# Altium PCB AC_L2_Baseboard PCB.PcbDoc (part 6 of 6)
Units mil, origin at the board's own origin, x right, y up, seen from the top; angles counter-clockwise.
Board outline 7290 x 7055 mil, 4 copper layers (Top Layer, Layer 1, Layer 2, Bottom Layer), stack 70.356 mil thick; 510 components, 285 nets, 1364 pads, 522 vias.
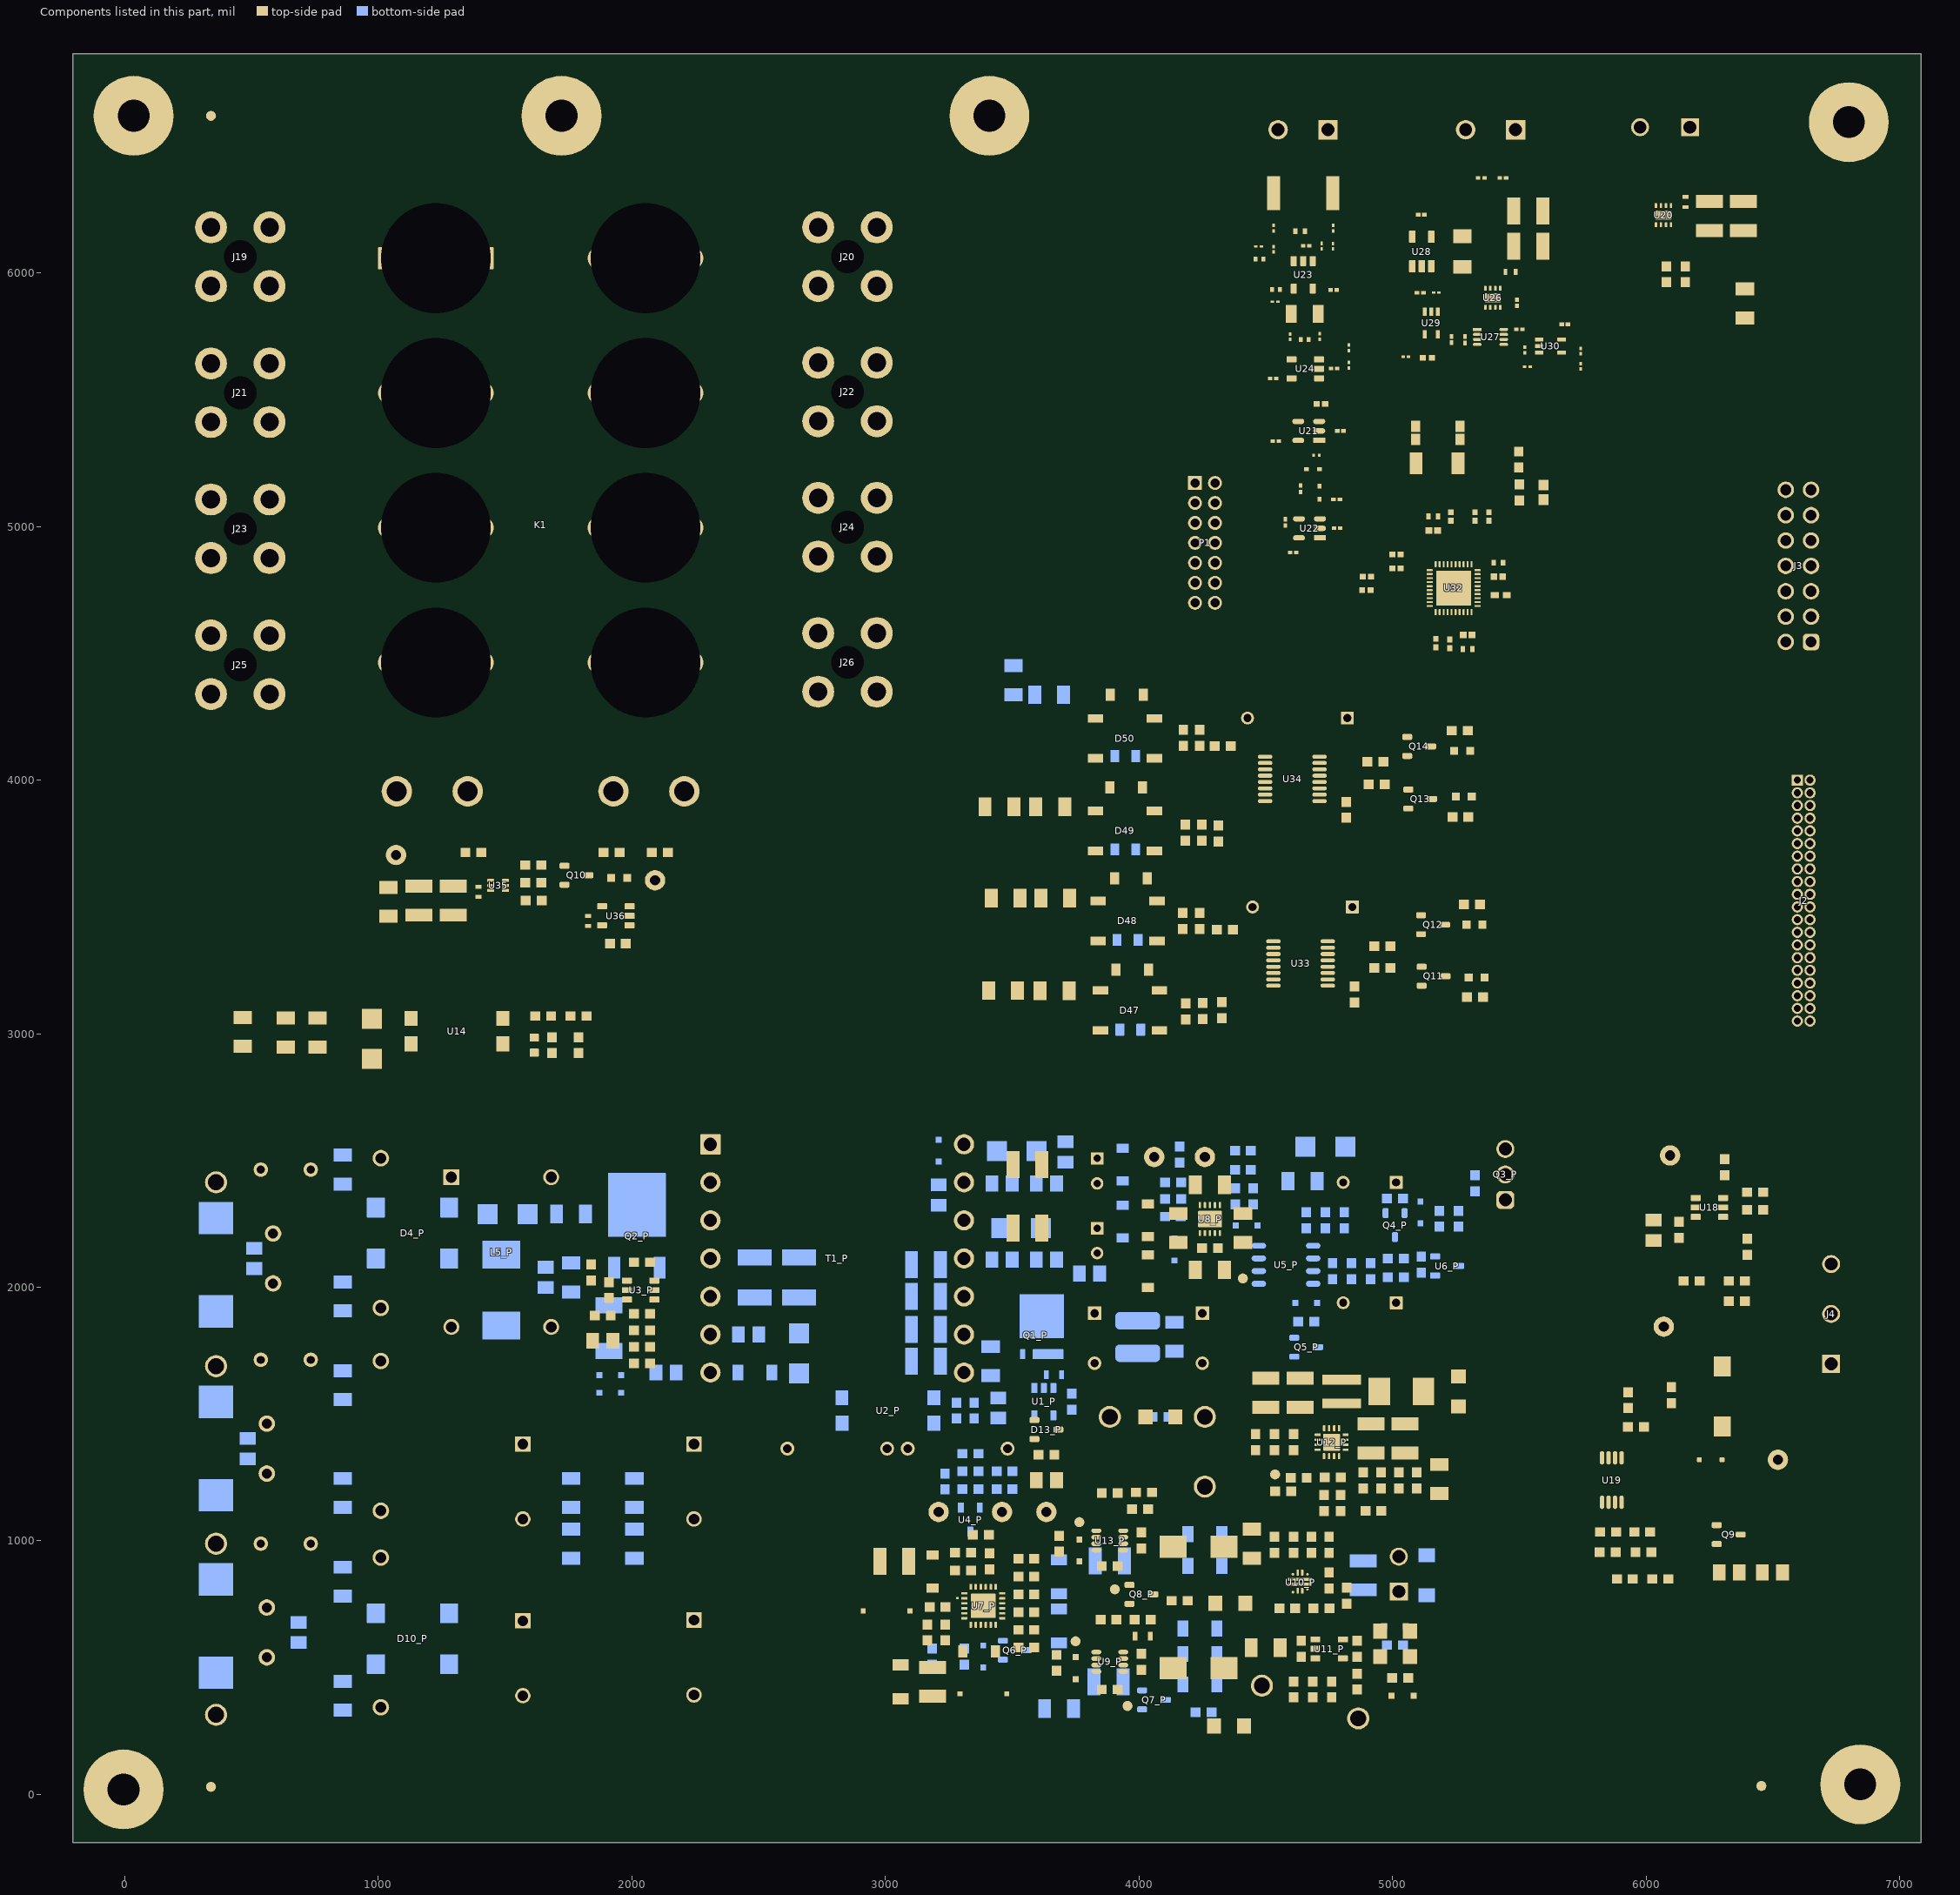
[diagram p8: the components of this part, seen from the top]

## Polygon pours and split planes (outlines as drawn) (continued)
NetC21_P_1 on Layer 2 "LAYER_2_NETC21_P_1_P1274" (solid, pour order 1274): 3195,2144 3270,2144 3290,2164 3355,2164 3700,1819 4070,1819 4080,1809 4080,1714 4005,1639 3205,1639 3190,1654 3190,2139
AGND1 on Layer 2 "LAYER_2_AGND1_P1262" (solid, pour order 1262): 3340,984 3560,984 3610,934 3610,714 3500,604 3372,604 3242,734 3166,734 3166,810
NetC38_P_1 on Layer 2 "LAYER_2_NETC38_P_1_P1272" (solid, pour order 1272): 4910,2464 4935,2489 5075.94,2489 5105.95,2459 5105.95,2134.95 4860,1889 4750.5,1889 4731,1908.5 4731,2110 4910,2289
Vbackup on Layer 2 "LAYER_2_VBACKUP_P1266" (solid, pour order 1266): 4635,2442 4682,2489 4860,2489 4885,2464 4885,2289 4710,2114 4710,1858.68 4735.79,1832.9 4866.1,1832.9 4885,1814 4885,1663.31 4480,1663.31 4480,2209 4635,2364
N_OUT on Layer 2 "LAYER_2_N_OUT_P1426" (solid, pour order 1426): 1825,4667.26 3030,4667.26 3070,4627.26 3070,4327.26 3015,4272.26 1825,4272.26 1785,4312.26 1785,4627.26
LINE3_OUT on Layer 2 "LAYER_2_LINE3_OUT_P1424" (solid, pour order 1424): 1832.5,5195 3037.5,5195 3077.5,5155 3077.5,4855 3022.5,4800 1832.5,4800 1792.5,4840 1792.5,5155
LINE2_OUT on Layer 2 "LAYER_2_LINE2_OUT_P1422" (solid, pour order 1422): 1820,5725 3025,5725 3065,5685 3065,5385 3010,5330 1820,5330 1780,5370 1780,5685
LINE1_OUT on Layer 2 "LAYER_2_LINE1_OUT_P1420" (solid, pour order 1420): 1809.7,6260 3014.7,6260 3054.7,6220 3054.7,5920 2999.7,5865 1809.7,5865 1769.7,5905 1769.7,6220
N_IN on Layer 2 "LAYER_2_N_IN_P1418" (solid, pour order 1418): 275,4655 1480,4655 1520,4615 1520,4315 1465,4260 275,4260 235,4300 235,4615
LINE3_IN on Layer 2 "LAYER_2_LINE3_IN_P1416" (solid, pour order 1416): 270,5185 1475,5185 1515,5145 1515,4845 1460,4790 270,4790 230,4830 230,5145
LINE2_IN on Layer 2 "LAYER_2_LINE2_IN_P1414" (solid, pour order 1414): 285,5730 1490,5730 1530,5690 1530,5390 1475,5335 285,5335 245,5375 245,5690
LINE1_IN on Layer 2 "LAYER_2_LINE1_IN_P1412" (solid, pour order 1412): 285,6265 1490,6265 1530,6225 1530,5925 1475,5870 285,5870 245,5910 245,6225
NetD4_P_4 on Layer 2 "LAYER_2_NETD4_P_4_P1282" (solid, pour order 1282): 940,2369 1045,2369 1045,2259 940,2259
NetC13_P_2 on Layer 2 "LAYER_2_NETC13_P_2_P1280" (solid, pour order 1280): 1485,1214 1485,589 2385,589 2385,1214
no net on Layer 2 "LAYER_2_NONET_P1278" (solid, pour order 1278): 1810,2589 2460,2589 2485,2564 2485,2364 2460,2339 2260,2339 2210,2289 2210,2214 2185,2189 1810,2189 1785,2214 1785,2564
NetC6_P_1 on Layer 2 "LAYER_2_NETC6_P_1_P1276" (solid, pour order 1276): 1825,1499 1585,1739 1585,2214 1735,2364 1735,2514 1710,2539 1485,2539 1360,2414 1360,2014 1410,1964 1410,1764 1335,1689 1335,1364 1410,1289 2335,1289 2530,1484 2530,1984 2475,2039 2235,2039 2235,1499
12V_In on Layer 2 "LAYER_2_12V_IN_P1270" (solid, pour order 1270): 3790,1979 4105,1979 4130,1954 4300,1954 4335,1919 4335,1454 4320,1439 4135,1439 4090,1484 4090,1829 3825,1829 3782.5,1829 3765,1840.67 3765,1954
NetC50_P_1 on Layer 2 "LAYER_2_NETC50_P_1_P1268" (solid, pour order 1268): 3560,464 3600,424 3600,274 3590,264 2935,264 2860,339 2860,589 2885,614 2985,614 3010,589 3135,464
AGND2 on Layer 2 "LAYER_2_AGND2_P1264" (solid, pour order 1264): 4675,1454 4870,1454 5010,1314 5010,1184 4960,1134 4635,1134 4610,1159 4610,1389
+12V on Layer 2 "LAYER_2_+12V_P1260" (solid, pour order 1260): 5135.5,1216.72 5138.23,1214 5260,1214 5285,1189 5285,1039 5260,1014 4960,1014 4785,839 4665,839 4606.22,780.22 4418.78,780.22 4410,789 4410,1039 4360,1089 4285,1089 3860,664 3660,664 3660,995.5 3853.5,1189 4185,1189 4210,1164 4310,1164 4360,1214 4535,1214 4560,1189 4560,1139 4585,1114 5024.62,1114 5127.35,1216.72
5V on Layer 2 "LAYER_2_5V_P1258" (solid, pour order 1258): 4259,1064 4385,1064 4385,739 4260,614 4110,464 4110,339 4035,264 3785,264 3760,289 3760,589 3810,639 3834,639

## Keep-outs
Keep-Out Layer:
  text ".Layer_Name" at 577,-858.49 h60

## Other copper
Top Layer:
  text ".Layer_Name" at 577,-858.49 h60
Layer 1:
  text ".Layer_Name" at 580,-850 h60
Layer 2:
  text ".Layer_Name" at 580,-850 h60
Bottom Layer:
  text ".Layer_Name" at 577,-858.49 h60

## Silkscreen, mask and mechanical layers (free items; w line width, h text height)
Top Overlay:
  lines w10: 1795,1500 1795,1665 1840,1710 1935,1710 1990,1655 1990,1615 1990,1490 1965,1465 1940,1440 1845,1440 ; 1990,1600 2040,1600 2055,1615 2055,1665 ; 2045,1655 2055,1665 ; 2065,1655 2055,1665 ; 2975,1165 3080,1165 ; 3060,1145 3080,1165 ; 3060,1185 3080,1165 ; 3075,550 3100,575 ; 3075,600 3100,575 ; 3520,495 3540,515 ; 3560,495 3540,515 ; 3905,230 3900,235 3900,265 4015,265 4065,315 4220,315 4230,305 ; 3930,285 3950,305 ; 3950,265 3950,305 ; 3955,195 3960,190 3995,190 4030,155 4030,60 4115,-25 4290,-25 4315,0 4315,195 4295,215 ; 3970,285 3950,305 ; 4430,2490 4445,2475 ; 4445,2640 4445,2475 ; 4460,2490 4445,2475 ; 4790,3160 4445,3160 4410,3130 4405,2675 4425,2650 4705,2650 4895,2840 4895,2985 4895,3025 ; 5175,575 5150,600 ; 5175,625 5150,600 ; 5200,600 5150,600 ; 5205,1350 5180,1375 ; 5205,1400 5180,1375 ; 5255,1375 5180,1375 ; 5260,1225 5260,1080 5300,1040 5615,1040 5740,1165 5740,1195 5740,1430 5660,1510 5420,1510 5375,1510 5260,1395 5260,1310 ; 5355,1565 5335,1585 ; 5355,1605 5335,1585 ; 5470,1690 5470,1585 5335,1585 ; 2900,450 3025,575 3100,575 ; 2900,450 2900,325 2925,300 2925,250 2800,125 2600,125 2575,150 2575,475 2600,500 2850,500 2900,450 ; 3540,515 3540,420 3580,380 ; 3580,380 3570,370 3570,40 3595,15 3910,15 3935,40 3935,190 3915,210 3835,210 3765,280 3765,355 3725,395 3595,395 3580,380 ; 2710,1050 2710,1180 2710,1185 2735,1210 2955,1210 2975,1190 2975,1050 2960,1035 2725,1035 2715,1045 2710,1050 ; 5235,265 5235,915 5235,950 5285,1000 5300,1000 5600,1000 5675,925 5675,800 5850,625 5925,625 5975,575 5975,250 5925,200 5300,200 5235,265 ; 5385,1690 5385,1795 5385,1905 5400,1905 5805,1905 5805,1690 5400,1690 5385,1690
  text "O1" at 6148,6762 h20
  text "O2" at 5957,6757 h20
  text "AC+" at 4708,6737 h20
  text "AC-" at 4535,6736 h20
  text "DC-" at 5261,6736 h20
  text "DC+" at 5450,6736 h20
  text "Plug" at 5683,6640 h50
  text "RCD DC" at 4880,6552 h50
  text "RCD AC" at 4148,6539 h50
  text "Lock" at 5681,6538 h50
  text "AC Input" at 275,6355 h60
  text "AC Output" at 2659,6355 h60
  text "L1" at 85,6066 h60
  text "L1" at 3117,6059 h60
  text "L2" at 77,5532 h60
  text "L2" at 3109,5525 h60
  text "E-meter" at 6486,5327 h50
  text "L3" at 69,4985 h60
  text "L3" at 3101,4978 h60
  text "N" at 77,4446 h60
  text "N" at 3109,4439 h60
  text "Weld Detection" at 4950,3655 h60
  text "Relay Drive" at 2175,3435 h60
  text "ZC HPGP" at 1899,2950.7 h60
  text "-12Va" at 3985,2640 h40
  text "+12Va" at 4205,2640 h40
  text "CP" at 6906,2069 h50
  text "PE" at 6907,1866 h50
  text "PP" at 6918,1673 h50
  text "GND" at 3800,1435 h40 r90
  text "+12Vp" at 4390,1405 h40 r90
  text "+5V" at 4210,1300 h40
  text "GND" at 5220,950 h40 r90
  text "12Vext" at 5215,705 h40 r90
  text "3.3V" at 4470,290 h40
  text "1.8V" at 4810,160 h40
  text ".Layer_Name" at 577,-858.49 h60
Bottom Overlay:
  lines w10: 2850,1250 3150,1250 ; 3125,1225 3150,1250 ; 3125,1275 3150,1250 ; 3210,1415 3210,1365 3155,1310 3155,1085 3235,1005 3510,1005 3560,1055 3560,1445 3505,1500 3505,1820 3485,1840 3360,1840 ; 3235,1595 3265,1625 ; 3302.5,1722.5 3345,1765 ; 4265,2315 4265,2445 ; 4280,2580 4315,2615 4325,2625 5300,2625 5325,2600 5365,2560 5365,2535 5365,2040 5275,1950 5050,1950 ; 4300,2260 4425,2135 4425,1850 4550,1725 4572.4,1725 ; 4715,1725 4800,1725 4975,1900 ; 5940,2046 5915,2071 ; 5940,2096 5915,2071 ; 6090,2071 5915,2071 ; 2480,580 2480,845 2515,880 2515,1085 2570,1140 2570,1175 2570,1200 2650,1280 2650,1320 2650,1340 2665,1355 2790,1355 2810,1335 2840,1305 2840,985 2865,960 2865,570 2840,545 2515,545 2480,580 ; 5915,2346 6090,2171 6090,1905 6274,1721 6390,1721 6665,1996 6915,1996 6965,2046 6965,2621 6965,2646 6940,2671 5965,2671 5915,2621 5915,2346
  text ".Layer_Name" at 577,-858.49 h60
Top Paste:
  text ".Layer_Name" at 577,-858.49 h60
Bottom Paste:
  text ".Layer_Name" at 577,-858.49 h60
Top Solder:
  text ".Layer_Name" at 577,-858.49 h60
  text ".Layer_Name" at 577,-858.49 h60
Bottom Solder:
  text ".Layer_Name" at 577,-858.49 h60
Drill Guide:
  text ".Layer_Name" at 577,-858.49 h60
M1 Board Outline:
  the board outline again, w10
  text ".Layer_Name" at 577,-858.49 h60
M2 Board Dimensions:
  rectangle: 0,-275 125,-150
  rectangle: 125,-400 500,-275
  lines w7: 0,-275 1000,-275 ; 125,-400 125,-150 ; 250,-400 250,-150 ; 500,-400 500,-150 ; 750,-400 750,-150 ; 0,-400 1000,-400 1000,-150 0,-150 0,-400
  text ".Layer_Name" at 577,-858.49 h60
M3 3D STEP Top:
  text ".Layer_Name" at 577,-858.49 h60
M4 3D STEP Bottom:
  text ".Layer_Name" at 577,-858.49 h60
M5 Assembly Top:
  circle w10: c2210,2564 r35.36
  lines w10: -292,-930.17 6308,-930.17 ; -292,-726.83 6310,-726.83 ; -292,-523.5 -292,-1133.5 3713,-1133.5 6310,-1133.5 6310,-523.5 -291.5,-523.5 -291.5,-1133.5 1284,-1133.5 ; 2173,-1133.5 2173,-523.5 ; 3440,-726.83 3440,-523.5 ; 4280,-726.83 4280,-523.5 ; 4902,-1140 4902,-937.17
  text "L1" at 185,2405 h60
  text "L2" at 165,1655 h60
  text "L3" at 160,970 h60
  text "N" at 215,285 h60
  text "COMPONENTS MARKED 'DNP' SHOULD NOT BE POPULATED." at 1153.5,-318.5 h60
  text "ASSEMBLY VARIANT:" at 1153,-434 h60
  text ".VariantName" at 2189,-434 h60
  text "PCB VIEWED FROM TOP SIDE" at -228.5,-655.67 h60
  text "BOARD #:" at 2248,-655.67 h60
  text ".PRJ_Number" at 2793.5,-655.67 h60
  text "REV:" at 3638,-655.67 h60
  text ".PCB_Rev" at 3929.5,-655.67 h60
  text "SVN REV:" at 4476,-655.67 h60
  text ".VersionControl_RevNumber" at 4982,-655.67 h60
  text "TID #:" at 2248,-859 h60
  text ".TID" at 2793.5,-859 h60
  text "PLOT NAME =" at -228.5,-1064.34 h60
  text ".plot_File_Name" at 577,-1064.34 h60
  text "GENERATED    :" at 2250,-1064.34 h60
  text ".Print_Date" at 3119.5,-1064.34 h60
  text ".Print_Time" at 3848.5,-1064.34 h60
  text "TEXAS INSTRUMENTS" at 5113,-1064.34 h60
M6 Assembly Bottom:
  lines w10: -292.5,-727.33 6309.5,-727.33 ; -290.5,-930.67 6309.5,-930.67 ; 1115.5,-1140.5 1115.5,-937.67 ; 1737.5,-727.33 1737.5,-524 ; 2577.5,-727.33 2577.5,-524 ; 3844.5,-1134 3844.5,-524 ; 4733.5,-1134 6309,-1134 6309,-524 -292.5,-524 -292.5,-1134 2304.5,-1134 6309.5,-1134 6309.5,-524
  text "COMPONENTS MARKED 'DNP' SHOULD NOT BE POPULATED." at 6102,-318 h60
  text ".VariantName" at 5058,-434 h60
  text "ASSEMBLY VARIANT:" at 6097,-434 h60
  text ".VersionControl_RevNumber" at 1035.5,-656.17 h60
  text "SVN REV:" at 1541.5,-656.17 h60
  text ".PCB_Rev" at 2088,-656.17 h60
  text "REV:" at 2379.5,-656.17 h60
  text ".PRJ_Number" at 3224,-656.17 h60
  text "BOARD #:" at 3769.5,-656.17 h60
  text "PCB VIEWED FROM BOTTOM SIDE" at 6246,-656.17 h60
  text ".TID" at 3224,-859.5 h60
  text "TID #:" at 3769.5,-859.5 h60
  text "TEXAS INSTRUMENTS" at 904.5,-1064.84 h60
  text ".Print_Time" at 2169,-1064.84 h60
  text ".Print_Date" at 2898,-1064.84 h60
  text "GENERATED    :" at 3767.5,-1064.84 h60
  text ".plot_File_Name" at 5440.5,-1064.84 h60
  text "PLOT NAME =" at 6246,-1064.84 h60
M9 Title Sheet:
  drawing of 57 lines, arcs and shapes, not listed
  text "1" at 539.84,8236.5 h70
  text "2" at 3035.5,8236.5 h70
  text "3" at 5524.84,8236.5 h70
  text "4" at 8031.51,8236.5 h70
  text "5" at 10530.5,8236.5 h70
  text "6" at 13035.5,8236.5 h70
  text "A" at -416.5,5193.5 h70
  text "A" at 14383.5,5193.5 h70
  text "B" at -416.5,4513.5 h70
  text "B" at 14383.5,4513.5 h70
  text "C" at -416.5,2138.5 h70
  text "C" at 14383.5,2138.5 h70
  text "PROJECT TITLE:" at 11343.5,277.5 h45
  text ".PRJ_Title" at 11393.5,144.17 h70
  text "DESIGNED FOR:" at 11343.5,-23.5 h45
  text ".PRJ_Customer" at 11393.5,-163.5 h70
  text "D" at -416.5,-231.5 h70
  text "D" at 14383.5,-231.5 h70
  text "FILE NAME:" at 11343.5,-323.5 h45
  text ".PCB_File_Name_No_Path" at 11393.5,-443.5 h70
  text "Texas Instruments (TI) and/or its licensors do not warrant the accuracy or completeness of this specification" at 6374,-605.34 h45
  text "ENGINEER:" at 11343.5,-613.5 h45
  text "LAYOUT BY:" at 12848.5,-613.5 h45
  text "or any information contained therein. TI and/or its licensors do not warrant that this design will meet" at 6329.01,-718 h45
  text ".PRJ_Engineer" at 11393.5,-768.49 h70
  text ".PCB_Layout" at 12899,-768.49 h70
  text "the specifications, will be suitable for your application or fit for any particular purpose, or will operate in" at 6329.01,-830.67 h45
  text ".Layer_Name" at 577,-858.49 h60
  text "ALTIUM DESIGNER VERSION:" at 12848.5,-923.5 h45
  text "an implementation. TI and/or its licensors do not warrant that the design is production worthy. You should" at 6329.01,-943.33 h45
  text "completely validate and test your design implementation to confirm the system functionality for your application." at 6374,-1056 h45
  text ".print_Scale" at 11393.5,-1056.83 h70
  text ".Application_BuildNumber" at 12899,-1056.83 h70
  text "1" at 739.84,-1263.5 h70
  text "2" at 3235.5,-1263.5 h70
  text "3" at 5724.84,-1263.5 h70
  text "4" at 8231.51,-1263.5 h70
  text "5" at 10730.5,-1263.5 h70
  text "6" at 13235.5,-1263.5 h70
M10 Fab Notes:
  drawing of 189 lines, arcs and shapes, not listed
  text "DESIGN INFORMATION" at 12368.02,6361.17 h60
  text "MIN. TRACK WIDTH:" at 11723.46,6229.05 h60
  text "8" at 12819.7,6229.05 h60
  text "MIL" at 12974.46,6229.05 h60
  text "MIN. CLEARANCE:" at 11737.46,6099.92 h60
  text "0.2" at 12773.7,6099.93 h60
  text "mm" at 12988.46,6099.92 h60
  text "MIN. VIA PAD SIZE:" at 11737.46,5975.8 h60
  text "24" at 12803.71,5975.8 h60
  text "MIL" at 12988.46,5975.8 h60
  text "0.05mm (2MIL)" at 12432.46,5845.9 h60
  text "MINIMUM ANNULAR RING" at 11408.23,5837.67 h60
  text "EXTERNAL" at 13140.46,5837.67 h60
  text "PER" at 11608.23,5727.55 h60
  text "IPC-D-275 CLASS 2 LEVEL C" at 11828.23,5727.54 h60
  text "MIL, HOLES" at 13316.46,5627.07 h60
  text "+/-" at 12924,5618.48 h60
  text "+/-" at 13778,5618.48 h60
  text "REGISTRATION TOLERANCES:" at 11408.23,5617.42 h60
  text "METAL" at 12608,5617.42 h60
  text "5" at 13184.2,5617.42 h60
  text "3" at 14017.2,5617.42 h60
  text "MIL" at 14133.46,5617.42 h60
  text "HOLE SIZE TOLERANCE (UNLESS OTHERWISE SPECIFIED):" at 11408.23,5519.1 h60
  text "+/-" at 13778,5516.23 h60
  text "3" at 14017.2,5515.17 h60
  text "MIL" at 14133.46,5515.17 h60
  text "MATERIAL:" at 11333.46,5377.52 h60
  text "FR-4 High Tg" at 12319.9,5249 h60
  text "X" at 12175.46,5241.01 h60
  text "FR-408" at 11754.46,5236.49 h60
  text "OTHER" at 13242.46,5236.49 h60
  text "62 MIL (1.6mm) +/-10%" at 12074.56,5093.46 h60
  text "X" at 11954.46,5091.01 h60
  text "THICKNESS:" at 11408.23,5085.24 h60
  text "OTHER" at 13359.46,5085.24 h60
  text "TOLERANCE:" at 11408.23,4946.92 h60
  text "X" at 12256.46,4946.92 h60
  text "ANSI IPC-6012 TYPE 3 CLASS 2" at 12434.48,4946.92 h60
  text "OTHER +/-" at 12434.46,4802.73 h60
  text "BOW & TWIST:" at 11408.23,4657.54 h60
  text "X" at 12256.46,4657.54 h60
  text "ANSI IPC-6012 TYPE 3 CLASS 2" at 12434.48,4657.54 h60
  text "OTHER +/-" at 12434.46,4510.85 h60
  text "DRILLING:" at 11333.46,4380.23 h60
  text "NC_DRILL FILES" at 13094.46,4275.04 h60
  text "REFERENCE:" at 11408.23,4271.1 h60
  text "X" at 12065.46,4271.01 h60
  text "AS SHOWN" at 12243.46,4271.1 h60
  text "X" at 12966.46,4271.1 h60
  text "OTHER" at 13392.46,4128.85 h60
  text "PTH COPPER THICKNESS:" at 11407.91,4125.32 h60
  text "X" at 12547.14,4125.32 h60
  text "20-30 um" at 12675.14,4125.32 h60
  text "BOARD FINISH:" at 11333.46,3977.73 h60
  text "SILKSCREEN:" at 11488.68,3867.6 h60
  text "X" at 12446.46,3867.6 h60
  text "TOP" at 12563.46,3867.6 h60
  text "X" at 12956.46,3867.6 h60
  text "BOTTOM" at 13074.46,3867.6 h60
  text "SILKSCREEN COLOR:" at 11488.68,3712.41 h60
  text "X" at 12445.46,3712.41 h60
  text "WHITE" at 12563.46,3712.41 h60
  text "OTHER" at 13074.46,3712.41 h60
  text "X" at 12576.46,3568.96 h60
  text "GREEN" at 12694.46,3568.96 h60
  text "OTHER" at 13312.46,3568.96 h60
  text "SOLDER RESIST COLOR:" at 11488.68,3562.1 h60
  text "X" at 12576.46,3414.71 h60
  text "MATTE" at 12694.46,3414.71 h60
  text "SEMI-GLOSS" at 13312,3414.07 h60
  text "IMMERSION GOLD (ENIG)" at 12394.46,3241.94 h60
  text "ENEPIG" at 13732,3234.72 h60
  text "SURFACE FINISH:" at 11333.46,3233.72 h60
  text "X" at 12216.46,3233.72 h60
  text "IMM. TIN/SILVER OR EQUIV" at 11663,3096.4 h60
  text "OTHER" at 13094.46,3092.47 h60
  text "ARRAY/PANEL:" at 11333.46,2937.09 h60
  text "CUT AND TRIM PER M1 BOARD OUTLINE" at 12394.46,2928.87 h60
  text "N.C. ROUTE" at 12394.46,2792.9 h60
  text "X" at 13082.46,2792.9 h60
  text "V. SCORE" at 13260.46,2792.9 h60
  text "CERTIFICATION:" at 11333.46,2663.77 h60
  text "MATERIALS AND WORKMANSHIP FOR ALL PCBS" at 12058.46,2663.77 h60
  text "TO MEET OR EXCEED THE REQUIREMENTS OF:" at 12058.46,2569.71 h60
  text "X" at 11695.97,2441.08 h60
  text "ANSI IPC-A-600F CLASS ->" at 11823.96,2441.08 h60
  text "X" at 13471.97,2441.08 h60
  text "2" at 13581.96,2441.08 h60
  text "1" at 13266.96,2439.58 h60
  text "3" at 13935.96,2439.58 h60
  text "X" at 12507.97,2293.39 h60
  text "RoHS" at 12635.96,2293.39 h60
  text "OTHER" at 13280.36,2293.39 h60
  text "PER ORDER" at 13677.42,2293.39 h60
  text "ALL BOARDS MUST MEET OR EXCEED UL94-V0 REQUIREMENTS." at 11361,2139.57 h60
  text "PCB MUST BEAR THE UL94V-0 UL REGISTERED MATERIAL ID NUMBER" at 11361,2023.5 h60
  text "ADDITIONAL REQUIREMENTS:" at 11333.46,1854.08 h60
  text "MICROSECTION:" at 11408.23,1746.95 h60
  text "YES" at 12313.96,1746.95 h60
  text "REQUIRED" at 13175.46,1602.62 h60
  text "BARE BOARD ELEC. TEST:" at 11408.23,1599.76 h60
  text "NONE" at 12713.96,1599.76 h60
  text "X" at 13057.46,1599.76 h60
  text "PER ORDER" at 13767.46,1599.76 h60
  text "XX MIL VIAS REQUIRE NON-CONDUCTIVE FILL AND PLANARIZE" at 11576.38,1394.82 h59
  text "XX MIL VIAS REQUIRE CONDUCTIVE FILL AND PLANARIZE" at 11584.38,1290.84 h60
  text "OUTER XX MIL TRACES REQUIRE 50 OHM SINGLE-ENDED IMPEDANCE" at 11583.39,1127.46 h58
  text "LAYER 2 & 3 (INNER LAYERS) XX MIL WIDE, XX MIL SPACE / TRACES REQUIRE 100 OHM DIFFERENTIAL IMPEDANCE" at 11575.39,891.74 h60
  text ".Layer_Name" at 577,-858.49 h60
M11 Gerber Information:
  lines w10: -292,-930.17 6308,-930.17 ; -292,-726.83 6310,-726.83 ; -292,-523.5 -292,-1133.5 3713,-1133.5 6310,-1133.5 6310,-523.5 -291.5,-523.5 -291.5,-1133.5 1284,-1133.5 ; 2173,-1133.5 2173,-523.5 ; 3440,-726.83 3440,-523.5 ; 4280,-726.83 4280,-523.5 ; 4902,-1140 4902,-937.17
  text "ALL ARTWORK VIEWED FROM TOP SIDE" at -228.5,-655.67 h60
  text "BOARD #:" at 2248,-655.67 h60
  text ".PRJ_Number" at 2793.5,-655.67 h60
  text "REV:" at 3638,-655.67 h60
  text ".PCB_Rev" at 3929.5,-655.67 h60
  text "SVN REV:" at 4476,-655.67 h60
  text ".VersionControl_RevNumber" at 4982,-655.67 h60
  text "LAYER NAME =" at -228.5,-858.49 h60
  text "TID #:" at 2248,-859 h60
  text ".TID" at 2793.5,-859 h60
  text "PLOT NAME =" at -228.5,-1064.34 h60
  text ".plot_File_Name" at 577,-1064.34 h60
  text "GENERATED    :" at 2250,-1064.34 h60
  text ".Print_Date" at 3119.5,-1064.34 h60
  text ".Print_Time" at 3848.5,-1064.34 h60
  text "TEXAS INSTRUMENTS" at 5113,-1064.34 h60
M12 Stackup:
  drawing of 295 lines, arcs and shapes, not listed
  text "Layer" at 26150.74,5930 h60
  text "Name" at 26560.65,5930 h60
  text "Material" at 27490.4,5930 h60
  text "Thickness" at 28350.16,5930 h60
  text "Constant" at 29000,5930 h60
  text "Board Layer Stack" at 29569.86,5930 h60
  text "1" at 26150.74,5810 h60
  text "Top Overlay" at 26560.65,5810 h60
  text "2" at 26150.74,5690 h60
  text "Top Solder" at 26560.65,5690 h60
  text "Solder Resist" at 27490.4,5690 h60
  text "0.40mil" at 28350.16,5690 h60
  text "3.5" at 29000,5690 h60
  text "3" at 26150.74,5570 h60
  text "Top Layer" at 26560.65,5570 h60
  text "Copper" at 27490.4,5570 h60
  text "1.40mil" at 28350.16,5570 h60
  text "4" at 26150.74,5450 h60
  text "Dielectric 1" at 26560.65,5450 h60
  text "PP-006" at 27490.4,5450 h60
  text "2.80mil" at 28350.16,5450 h60
  text "4.1" at 29000,5450 h60
  text "5" at 26150.74,5330 h60
  text "Layer 1" at 26560.65,5330 h60
  text "Copper" at 27490.4,5330 h60
  text "1.38mil" at 28350.16,5330 h60
  text "6" at 26150.74,5210 h60
  text "Dielectric1" at 26560.65,5210 h60
  text "FR-4" at 27490.4,5210 h60
  text "59.20mil" at 28350.16,5210 h60
  text "4.8" at 29000,5210 h60
  text "7" at 26150.74,5090 h60
  text "Layer 2" at 26560.65,5090 h60
  text "Copper" at 27490.4,5090 h60
  text "1.38mil" at 28350.16,5090 h60
  text "8" at 26150.74,4970 h60
  text "Dielectric 2" at 26560.65,4970 h60
  text "PP-006" at 27490.4,4970 h60
  text "2.80mil" at 28350.16,4970 h60
  text "4.1" at 29000,4970 h60
  text "9" at 26150.74,4850 h60
  text "Bottom Layer" at 26560.65,4850 h60
  text "Copper" at 27490.4,4850 h60
  text "1.40mil" at 28350.16,4850 h60
  text "10" at 26150.74,4730 h60
  text "Bottom Solder" at 26560.65,4730 h60
  text "Solder Resist" at 27490.4,4730 h60
  text "0.40mil" at 28350.16,4730 h60
  text "3.5" at 29000,4730 h60
  text "11" at 26150.74,4610 h60
  text "Bottom Overlay" at 26560.65,4610 h60
  text ".Layer_Name" at 577,-858.49 h60
M13 Component Bodies Top:
  text ".Layer_Name" at 577,-858.49 h60
M14 Component Bodies Bottom:
  text ".Layer_Name" at 577,-858.49 h60
M15 Courtyards Top:
  text ".Layer_Name" at 577,-858.49 h60
M16 Courtyards Bottom:
  text ".Layer_Name" at 577,-858.49 h60
Drill Drawing:
  drawing of 184 lines, arcs and shapes, not listed
  text "Symbol" at 31590.42,6818.94 h72
  text "Quantity" at 31890.57,6818.94 h72
  text "Finished Hole Size" at 32222.26,6818.94 h72
  text "Plated" at 32858.12,6818.94 h72
  text "Hole Type" at 33116.92,6818.94 h72
  text "Drill Layer Pair" at 33491.67,6818.94 h72
  text "Hole Tolerance" at 34214.21,6818.94 h72
  text "8" at 31890.57,6694.92 h60
  text "129.92mil (3.300mm)" at 32222.26,6694.92 h60
  text "NPTH" at 32858.12,6694.92 h60
  text "Round" at 33116.92,6694.92 h60
  text "Top Layer - Bottom Layer" at 33491.67,6694.92 h60
  text "B" at 31565.17,6684.93 h55.12
  text "29" at 31890.57,6570.89 h60
  text "7.87mil (0.200mm)" at 32222.26,6570.89 h60
  text "PTH" at 32858.12,6570.89 h60
  text "Round" at 33116.92,6570.89 h60
  text "Top Layer - Bottom Layer" at 33491.67,6570.89 h60
  text "209" at 31890.57,6446.86 h60
  text "8.00mil (0.203mm)" at 32222.26,6446.86 h60
  text "PTH" at 32858.12,6446.86 h60
  text "Round" at 33116.92,6446.86 h60
  text "Top Layer - Bottom Layer" at 33491.67,6446.86 h60
  text "A" at 31565.17,6436.87 h55.12
  text "5" at 31890.57,6322.84 h60
  text "12.00mil (0.305mm)" at 32222.26,6322.84 h60
  text "PTH" at 32858.12,6322.84 h60
  text "Round" at 33116.92,6322.84 h60
  text "Top Layer - Bottom Layer" at 33491.67,6322.84 h60
  text "231" at 31890.57,6198.81 h60
  text "16.00mil (0.406mm)" at 32222.26,6198.81 h60
  text "PTH" at 32858.12,6198.81 h60
  text "Round" at 33116.92,6198.81 h60
  text "Top Layer - Bottom Layer" at 33491.67,6198.81 h60
  text "40" at 31890.57,6074.78 h60
  text "27.95mil (0.710mm)" at 32222.26,6074.78 h60
  text "PTH" at 32858.12,6074.78 h60
  text "Round" at 33116.92,6074.78 h60
  text "Top Layer - Bottom Layer" at 33491.67,6074.78 h60
  text "F" at 31565.17,6064.79 h55.12
  text "48" at 31890.57,5950.76 h60
  text "28.00mil (0.711mm)" at 32222.26,5950.76 h60
  text "PTH" at 32858.12,5950.76 h60
  text "Round" at 33116.92,5950.76 h60
  text "Top Layer - Bottom Layer" at 33491.67,5950.76 h60
  text "4" at 31890.57,5826.73 h60
  text "29.53mil (0.750mm)" at 32222.26,5826.73 h60
  text "PTH" at 32858.12,5826.73 h60
  text "Round" at 33116.92,5826.73 h60
  text "Top Layer - Bottom Layer" at 33491.67,5826.73 h60
  text "14" at 31890.57,5702.7 h60
  text "31.50mil (0.800mm)" at 32222.26,5702.7 h60
  text "PTH" at 32858.12,5702.7 h60
  text "Round" at 33116.92,5702.7 h60
  text "Top Layer - Bottom Layer" at 33491.67,5702.7 h60
  text "4" at 31890.57,5578.68 h60
  text "33.47mil (0.850mm)" at 32222.26,5578.68 h60
  text "PTH" at 32858.12,5578.68 h60
  text "Round" at 33116.92,5578.68 h60
  text "Top Layer - Bottom Layer" at 33491.67,5578.68 h60
  text "18" at 31890.57,5454.65 h60
  text "35.43mil (0.900mm)" at 32222.26,5454.65 h60
  text "PTH" at 32858.12,5454.65 h60
  text "Round" at 33116.92,5454.65 h60
  text "Top Layer - Bottom Layer" at 33491.67,5454.65 h60
  text "6" at 31890.57,5330.62 h60
  text "39.37mil (1.000mm)" at 32222.26,5330.62 h60
  text "PTH" at 32858.12,5330.62 h60
  text "Round" at 33116.92,5330.62 h60
  text "Top Layer - Bottom Layer" at 33491.67,5330.62 h60
  text "10" at 31890.57,5206.6 h60
  text "40.00mil (1.016mm)" at 32222.26,5206.6 h60
  text "PTH" at 32858.12,5206.6 h60
  text "Round" at 33116.92,5206.6 h60
  text "Top Layer - Bottom Layer" at 33491.67,5206.6 h60
  text "8" at 31890.57,5082.57 h60
  text "41.34mil (1.050mm)" at 32222.26,5082.57 h60
  text "PTH" at 32858.12,5082.57 h60
  text "Round" at 33116.92,5082.57 h60
  text "Top Layer - Bottom Layer" at 33491.67,5082.57 h60
  text "10" at 31890.57,4958.54 h60
  text "43.31mil (1.100mm)" at 32222.26,4958.54 h60
  text "PTH" at 32858.12,4958.54 h60
  text "Round" at 33116.92,4958.54 h60
  text "Top Layer - Bottom Layer" at 33491.67,4958.54 h60
  text "14" at 31890.57,4834.52 h60
  text "43.31mil (1.100mm)" at 32222.26,4834.52 h60
  text "PTH" at 32858.12,4834.52 h60
  text "Round" at 33116.92,4834.52 h60
  text "Top Layer - Bottom Layer" at 33491.67,4834.52 h60
  text "+/-1.97mil" at 34214.21,4834.52 h60
  text "I" at 31574.36,4824.53 h55.12
  text "14" at 31890.57,4710.49 h60
  text "51.18mil (1.300mm)" at 32222.26,4710.49 h60
  text "PTH" at 32858.12,4710.49 h60
  text "Round" at 33116.92,4710.49 h60
  text "Top Layer - Bottom Layer" at 33491.67,4710.49 h60
  text "14" at 31890.57,4586.46 h60
  text "51.97mil (1.320mm)" at 32222.26,4586.46 h60
  text "PTH" at 32858.12,4586.46 h60
  text "Round" at 33116.92,4586.46 h60
  text "Top Layer - Bottom Layer" at 33491.67,4586.46 h60
  text "9" at 31890.57,4462.44 h60
  text "63.00mil (1.600mm)" at 32222.26,4462.44 h60
  text "PTH" at 32858.12,4462.44 h60
  text "Round" at 33116.92,4462.44 h60
  text "Top Layer - Bottom Layer" at 33491.67,4462.44 h60
  text "32" at 31890.57,4338.41 h60
  text "72.84mil (1.850mm)" at 32222.26,4338.41 h60
  text "PTH" at 32858.12,4338.41 h60
  text "Round" at 33116.92,4338.41 h60
  text "Top Layer - Bottom Layer" at 33491.67,4338.41 h60
  text "C" at 31565.17,4328.42 h55.12
  text "4" at 31890.57,4214.38 h60
  text "78.74mil (2.000mm)" at 32222.26,4214.38 h60
  text "PTH" at 32858.12,4214.38 h60
  text "Round" at 33116.92,4214.38 h60
  text "Top Layer - Bottom Layer" at 33491.67,4214.38 h60
  text "D" at 31565.17,4204.39 h55.12
  text "6" at 31890.57,4090.36 h60
  text "125.98mil (3.200mm)" at 32222.26,4090.36 h60
  text "PTH" at 32858.12,4090.36 h60
  text "Round" at 33116.92,4090.36 h60
  text "Top Layer - Bottom Layer" at 33491.67,4090.36 h60
  text "G" at 31565.17,4080.37 h55.12
  text "8" at 31890.57,3966.33 h60
  text "433.07mil (11.000mm)" at 32222.26,3966.33 h60
  text "PTH" at 32858.12,3966.33 h60
  text "Slot" at 33116.92,3966.33 h60
  text "Top Layer - Bottom Layer" at 33491.67,3966.33 h60
  text "E" at 31565.17,3956.34 h55.12
  text "745 Total" at 31890.57,3842.3 h60
  text "Slot definitions :" at 31590.42,3755.49 h60
  text "Routed Path Length" at 32039.86,3755.49 h60
  text "= Calculated from tool start centre position to tool end centre position." at 32578.21,3755.49 h60
  text "Hole Length" at 32039.86,3705.87 h60
  text "= Routed Path Length + Tool Size = Slot length as defined in the PCB layout" at 32378.91,3705.87 h60
  text ".Layer_Name" at 577,-858.49 h60
M17 Embedded Cavity:
  text ".Layer_Name" at 577,-858.49 h60
M18 Embedded Assembly:
  text ".Layer_Name" at 577,-858.49 h60
M19 Embedded Keepout:
  text ".Layer_Name" at 577,-858.49 h60

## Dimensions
0,-400 to 1000,-400 on M2 Board Dimensions
0,0 to -205,6865 on M2 Board Dimensions
-10,-30 to 7085,-190 on M2 Board Dimensions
